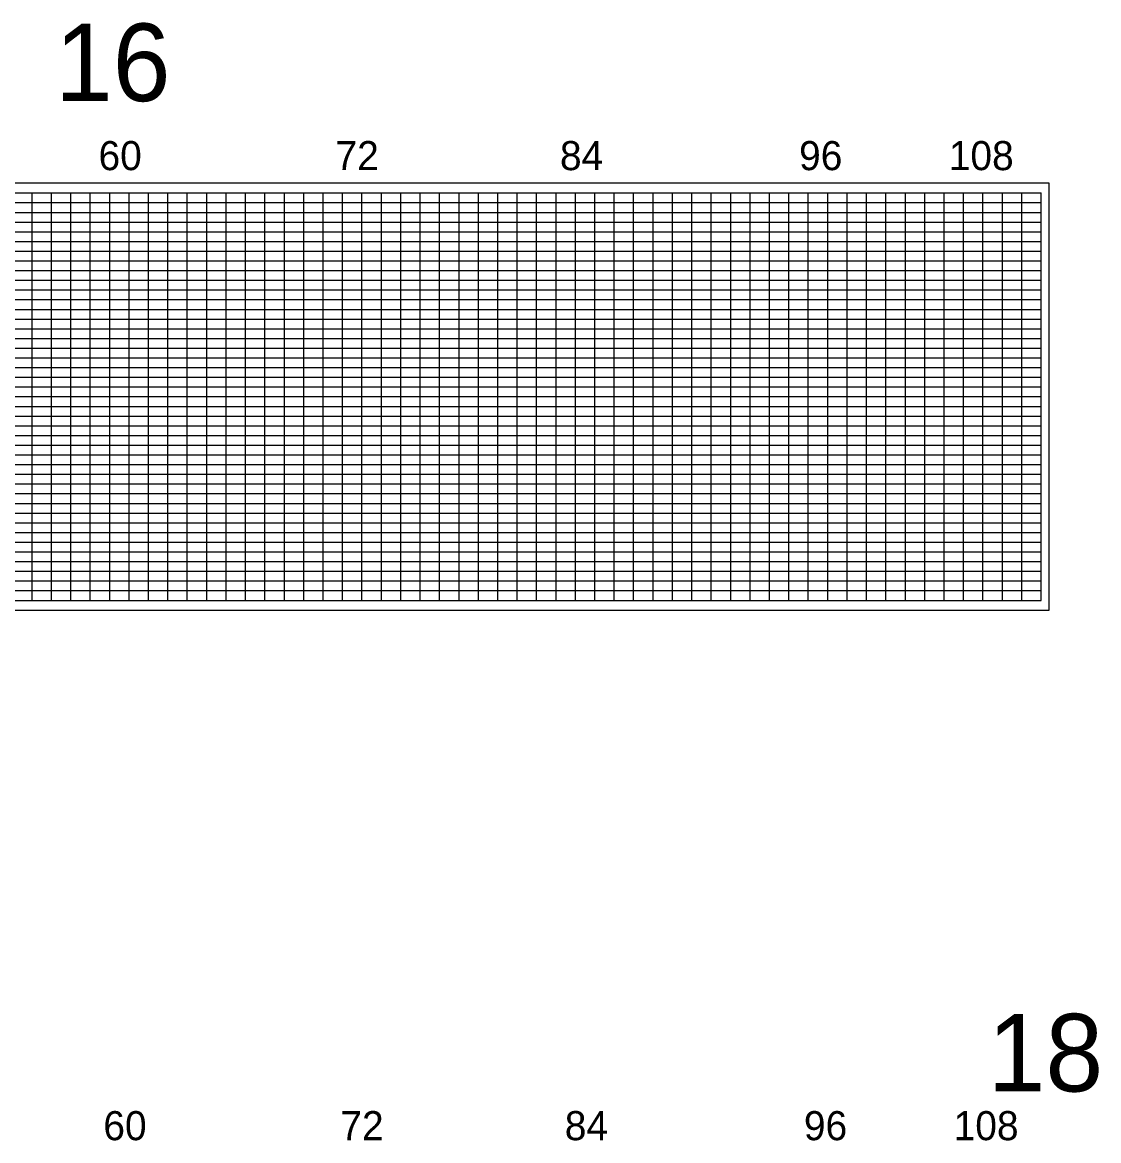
# Model space of a CAD drawing. Extents: x 1914168 to 1925341, y 720939 to 777401.
# Drawn here: x 1922568 to 1925341, y 739572 to 742454 of the extents above; entities that cross this region are included whole.
import ezdxf

# ---------------------------------------------------------------- set-up
doc = ezdxf.new("R2010")
doc.units = 0
for name, color, linetype in [('RD_PD_ALT1_CL', 7, 'Continuous'), ('RD_PD_WallFill', 7, 'Continuous'), ('RD_SHT_IplotShp', 7, 'Continuous')]:
    doc.layers.add(name, color=color, linetype=linetype)

msp = doc.modelspace()

# ---------------------------------------------------------------- linework, layer by layer
at = {"layer": 'RD_PD_WallFill'}
for p, q in [((1919842.5, 742014.2), (1925192.5, 742014.2)), ((1922592.5, 740964.2), (1922592.5, 742014.2)), ((1922592.5, 740964.2), (1922592.5, 742014.2)), ((1922642.5, 740964.2), (1922642.5, 742014.2)), ((1922642.5, 740964.2), (1922642.5, 742014.2)), ((1922692.5, 740964.2), (1922692.5, 742014.2)), ((1922692.5, 740964.2), (1922692.5, 742014.2)), ((1922742.5, 740964.2), (1922742.5, 742014.2)), ((1922742.5, 740964.2), (1922742.5, 742014.2)), ((1922792.5, 740964.2), (1922792.5, 742014.2)), ((1922792.5, 740964.2), (1922792.5, 742014.2)), ((1922842.5, 740964.2), (1922842.5, 742014.2)), ((1922842.5, 740964.2), (1922842.5, 742014.2)), ((1922892.5, 740964.2), (1922892.5, 742014.2)), ((1922892.5, 740964.2), (1922892.5, 742014.2)), ((1922942.5, 740964.2), (1922942.5, 742014.2)), ((1922942.5, 740964.2), (1922942.5, 742014.2)), ((1922992.5, 740964.2), (1922992.5, 742014.2)), ((1922992.5, 740964.2), (1922992.5, 742014.2)), ((1923042.5, 740964.2), (1923042.5, 742014.2)), ((1923042.5, 740964.2), (1923042.5, 742014.2)), ((1923092.5, 740964.2), (1923092.5, 742014.2)), ((1923092.5, 740964.2), (1923092.5, 742014.2)), ((1923142.5, 740964.2), (1923142.5, 742014.2)), ((1923142.5, 740964.2), (1923142.5, 742014.2)), ((1923192.5, 740964.2), (1923192.5, 742014.2)), ((1923192.5, 740964.2), (1923192.5, 742014.2)), ((1923242.5, 740964.2), (1923242.5, 742014.2)), ((1923242.5, 740964.2), (1923242.5, 742014.2)), ((1923292.5, 740964.2), (1923292.5, 742014.2)), ((1923292.5, 740964.2), (1923292.5, 742014.2)), ((1923342.5, 740964.2), (1923342.5, 742014.2)), ((1923342.5, 740964.2), (1923342.5, 742014.2)), ((1923392.5, 740964.2), (1923392.5, 742014.2)), ((1923392.5, 740964.2), (1923392.5, 742014.2)), ((1923442.5, 740964.2), (1923442.5, 742014.2)), ((1923442.5, 740964.2), (1923442.5, 742014.2)), ((1923492.5, 740964.2), (1923492.5, 742014.2)), ((1923492.5, 740964.2), (1923492.5, 742014.2)), ((1923542.5, 740964.2), (1923542.5, 742014.2)), ((1923542.5, 740964.2), (1923542.5, 742014.2)), ((1923592.5, 740964.2), (1923592.5, 742014.2)), ((1923592.5, 740964.2), (1923592.5, 742014.2)), ((1923642.5, 740964.2), (1923642.5, 742014.2)), ((1923642.5, 740964.2), (1923642.5, 742014.2)), ((1923692.5, 740964.2), (1923692.5, 742014.2)), ((1923692.5, 740964.2), (1923692.5, 742014.2)), ((1923742.5, 740964.2), (1923742.5, 742014.2)), ((1923742.5, 740964.2), (1923742.5, 742014.2)), ((1923792.5, 740964.2), (1923792.5, 742014.2)), ((1923792.5, 740964.2), (1923792.5, 742014.2)), ((1923842.5, 740964.2), (1923842.5, 742014.2)), ((1923842.5, 740964.2), (1923842.5, 742014.2)), ((1923892.5, 740964.2), (1923892.5, 742014.2)), ((1923892.5, 740964.2), (1923892.5, 742014.2)), ((1923942.5, 740964.2), (1923942.5, 742014.2)), ((1923942.5, 740964.2), (1923942.5, 742014.2)), ((1923992.5, 740964.2), (1923992.5, 742014.2)), ((1923992.5, 740964.2), (1923992.5, 742014.2)), ((1924042.5, 740964.2), (1924042.5, 742014.2)), ((1924042.5, 740964.2), (1924042.5, 742014.2)), ((1924092.5, 740964.2), (1924092.5, 742014.2)), ((1924092.5, 740964.2), (1924092.5, 742014.2)), ((1924142.5, 740964.2), (1924142.5, 742014.2)), ((1924142.5, 740964.2), (1924142.5, 742014.2)), ((1924192.5, 740964.2), (1924192.5, 742014.2)), ((1924192.5, 740964.2), (1924192.5, 742014.2)), ((1924242.5, 740964.2), (1924242.5, 742014.2)), ((1924242.5, 740964.2), (1924242.5, 742014.2)), ((1924292.5, 740964.2), (1924292.5, 742014.2)), ((1924292.5, 740964.2), (1924292.5, 742014.2)), ((1924342.5, 740964.2), (1924342.5, 742014.2)), ((1924342.5, 740964.2), (1924342.5, 742014.2)), ((1924392.5, 740964.2), (1924392.5, 742014.2)), ((1924392.5, 740964.2), (1924392.5, 742014.2)), ((1924442.5, 740964.2), (1924442.5, 742014.2)), ((1924442.5, 740964.2), (1924442.5, 742014.2)), ((1924492.5, 740964.2), (1924492.5, 742014.2)), ((1924492.5, 740964.2), (1924492.5, 742014.2)), ((1924542.5, 740964.2), (1924542.5, 742014.2)), ((1924542.5, 740964.2), (1924542.5, 742014.2)), ((1924592.5, 740964.2), (1924592.5, 742014.2)), ((1924592.5, 740964.2), (1924592.5, 742014.2)), ((1924642.5, 740964.2), (1924642.5, 742014.2)), ((1924642.5, 740964.2), (1924642.5, 742014.2)), ((1924692.5, 740964.2), (1924692.5, 742014.2)), ((1924692.5, 740964.2), (1924692.5, 742014.2)), ((1924742.5, 740964.2), (1924742.5, 742014.2)), ((1924742.5, 740964.2), (1924742.5, 742014.2)), ((1924792.5, 740964.2), (1924792.5, 742014.2)), ((1924792.5, 740964.2), (1924792.5, 742014.2)), ((1924842.5, 740964.2), (1924842.5, 742014.2)), ((1924842.5, 740964.2), (1924842.5, 742014.2)), ((1924892.5, 740964.2), (1924892.5, 742014.2)), ((1924892.5, 740964.2), (1924892.5, 742014.2)), ((1924942.5, 740964.2), (1924942.5, 742014.2)), ((1924942.5, 740964.2), (1924942.5, 742014.2)), ((1924992.5, 740964.2), (1924992.5, 742014.2)), ((1924992.5, 740964.2), (1924992.5, 742014.2)), ((1925042.5, 740964.2), (1925042.5, 742014.2)), ((1925042.5, 740964.2), (1925042.5, 742014.2)), ((1925092.5, 740964.2), (1925092.5, 742014.2)), ((1925092.5, 740964.2), (1925092.5, 742014.2)), ((1925142.5, 740964.2), (1925142.5, 742014.2)), ((1925142.5, 740964.2), (1925142.5, 742014.2)), ((1925192.5, 740964.2), (1925192.5, 742014.2)), ((1925192.5, 740964.2), (1925192.5, 742014.2)), ((1920292.5, 741989.2), (1925192.5, 741989.2)), ((1920292.5, 741989.2), (1925192.5, 741989.2)), ((1920292.5, 741964.2), (1925192.5, 741964.2)), ((1920292.5, 741939.2), (1925192.5, 741939.2)), ((1920292.5, 741914.2), (1925192.5, 741914.2)), ((1920292.5, 741889.2), (1925192.5, 741889.2)), ((1919842.5, 741864.2), (1925192.5, 741864.2)), ((1919842.5, 741839.2), (1925192.5, 741839.2)), ((1919842.5, 741814.2), (1925192.5, 741814.2)), ((1919842.5, 741789.2), (1925192.5, 741789.2)), ((1919842.5, 741764.2), (1925192.5, 741764.2)), ((1919842.5, 741739.2), (1925192.5, 741739.2)), ((1919842.5, 741714.2), (1925192.5, 741714.2)), ((1919842.5, 741689.2), (1925192.5, 741689.2)), ((1919842.5, 741664.2), (1925192.5, 741664.2)), ((1919842.5, 741639.2), (1925192.5, 741639.2)), ((1919842.5, 741614.2), (1925192.5, 741614.2)), ((1919842.5, 741589.2), (1925192.5, 741589.2)), ((1919842.5, 741564.2), (1925192.5, 741564.2)), ((1919842.5, 741539.2), (1925192.5, 741539.2)), ((1919842.5, 741514.2), (1925192.5, 741514.2)), ((1919842.5, 741489.2), (1925192.5, 741489.2)), ((1919842.5, 741464.2), (1925192.5, 741464.2)), ((1919842.5, 741439.2), (1925192.5, 741439.2)), ((1919842.5, 741414.2), (1925192.5, 741414.2)), ((1919842.5, 741389.2), (1925192.5, 741389.2)), ((1919842.5, 741364.2), (1925192.5, 741364.2)), ((1919842.5, 741339.2), (1925192.5, 741339.2)), ((1919842.5, 741314.2), (1925192.5, 741314.2)), ((1919842.5, 741289.2), (1925192.5, 741289.2)), ((1919842.5, 741264.2), (1925192.5, 741264.2)), ((1919842.5, 741239.2), (1925192.5, 741239.2)), ((1919842.5, 741214.2), (1925192.5, 741214.2)), ((1919842.5, 741189.2), (1925192.5, 741189.2)), ((1919842.5, 741164.2), (1925192.5, 741164.2)), ((1919842.5, 741139.2), (1925192.5, 741139.2)), ((1919842.5, 741114.2), (1925192.5, 741114.2)), ((1919842.5, 741089.2), (1925192.5, 741089.2)), ((1919842.5, 741064.2), (1925192.5, 741064.2)), ((1919842.5, 741039.2), (1925192.5, 741039.2)), ((1919842.5, 741014.2), (1925192.5, 741014.2)), ((1919842.5, 740989.2), (1925192.5, 740989.2)), ((1919842.5, 740964.2), (1925192.5, 740964.2)), ((1919842.5, 740964.2), (1925192.5, 740964.2))]:
    msp.add_line(p, q, dxfattribs=at)
at = {"layer": 'RD_SHT_IplotShp'}
msp.add_lwpolyline([(1919813.4, 740939.1), (1925213.4, 740939.1), (1925213.4, 742039.1), (1919813.4, 742039.1)], close=True, dxfattribs=at)

# ---------------------------------------------------------------- texts
at = {"layer": 'RD_PD_ALT1_CL'}
for s, p in [('16', (1922651.6, 742250.8)), ('18', (1925054.7, 739698.5))]:
    msp.add_text(s, height=200, dxfattribs=at).set_placement(p)
at = {"layer": 'RD_PD_WallFill'}
for s, p in [('60', (1922763.7, 742072.9)), ('60', (1922763.7, 742072.9)), ('72', (1923374.3, 742072.9)), ('72', (1923374.3, 742072.9)), ('84', (1923952.6, 742072.9)), ('84', (1923952.6, 742072.9)), ('96', (1924568.7, 742072.9)), ('96', (1924568.7, 742072.9)), ('108', (1924954.4, 742072.9)), ('60', (1922776.1, 739572.9)), ('60', (1922776.1, 739572.9)), ('72', (1923386.8, 739572.9)), ('72', (1923386.8, 739572.9)), ('84', (1923965, 739572.9)), ('84', (1923965, 739572.9)), ('96', (1924581.1, 739572.9)), ('96', (1924581.1, 739572.9)), ('108', (1924966.9, 739572.9))]:
    msp.add_text(s, height=75, dxfattribs=at).set_placement(p)

doc.saveas('drawing.dxf')
